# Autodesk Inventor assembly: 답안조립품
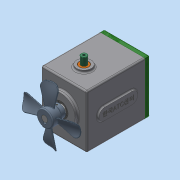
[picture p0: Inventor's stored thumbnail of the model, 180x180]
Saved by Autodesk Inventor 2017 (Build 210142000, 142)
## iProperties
Part Number: 답안조립품
Material: 일반
Document SubType Name: Assembly
Designer: MRC
Mass: 2669.46 g
Surface Area: 1952.92 cm^2
Volume: 798.897 cm^3
Density: 3.34143 g/cm^3
Author: MRC
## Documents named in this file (17)
- C:\Users\MRC\Desktop\610205V1007\답안조립품.iam
- C:\Users\MRC\Desktop\610205V1007\본체.ipt
- C:\Users\MRC\Desktop\610205V1007\가변스프링.ipt
- C:\Users\MRC\Desktop\610205V1007\멈춤나사 M3x8.ipt
- C:\Users\MRC\Desktop\610205V1007\메인 기어 축.ipt
- C:\Users\MRC\Desktop\610205V1007\베어링 608.ipt
- C:\Users\MRC\Desktop\610205V1007\베어링 6903.ipt
- C:\Users\MRC\Desktop\610205V1007\볼트 M4 x 10.ipt
- C:\Users\MRC\Desktop\610205V1007\부시.ipt
- C:\Users\MRC\Desktop\610205V1007\서브 기어 축.ipt
- C:\Users\MRC\Desktop\610205V1007\슬라이더.ipt
- C:\Users\MRC\Desktop\610205V1007\오일 실 8 22 7.ipt
- C:\Users\MRC\Desktop\610205V1007\오일 실 17 30 8.ipt
- C:\Users\MRC\Desktop\610205V1007\커버.ipt
- C:\Users\MRC\Desktop\610205V1007\키 5 x 5 x 24.ipt
- C:\Users\MRC\Desktop\610205V1007\팬날개.ipt
- 팬날개.ipt
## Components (1 placed, 1 different names)
1. 가변스프링:1
